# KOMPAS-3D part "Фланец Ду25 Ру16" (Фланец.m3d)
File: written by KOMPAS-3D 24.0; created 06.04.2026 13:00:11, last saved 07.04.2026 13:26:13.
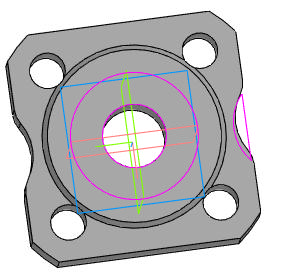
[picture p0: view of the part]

Document properties: Автор: R2D2; Полное имя файла: E:\Работа\Зайцев\Солянка\VSR1-13V-PED-F Клапан запорно-регулирующий DN.ru\DN25\исходные материалы\Фланец.m3d

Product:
- Component [standard]: (unnamed)  | qty 1  | Материал: ВЧ40 ГОСТ 7293-85 (density 7200 kg/m3); Масса: 1.17; additional columns: 25-16-01-1-B-ВЧ40-II-dв 33; Фланец квадратный; ГОСТ 33259-2015
- Part/product: Фланец Ду25 Ру16
    Масса: 0.888787

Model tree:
1. Эскиз:1
2. Элемент выдавливания:1
3. Скругление:1  (with: Ребро.Элемент выдавливания:1)
     Радиус = 10
4. Зеркальный массив:1
5. Экземпляр ( 1 )
6. Экземпляр ( 2 )  (with: Элемент выдавливания:1, Скругление:1)
7. Эскиз:2
8. Элемент выдавливания:2
     Расстояние 1 = -18

Expressions: v108*2
Referenced files in C:\Program Files\ASCON\KOMPAS-3D v24\Libs\PolynomLib\DATA\vault\Methods\Kompas\3D\: PLib_Flange_GOST_33259_1401.m3d
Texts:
  BOSimple***Material:38d6725a-5efe-48e1-b177-a7817acb862a
  BOSimple***PART:3d5c1697-8c1a-4a41-919e-241c28f704d4***SHORTLOC:B6A6_23E38AE8DB154823[II;1;Квадратный;25;16;33;0;ВЧ40 ГОСТ 7293-85]
  Ch34
  Плоскость XY.Начало координат
  Ось Z.Начало координат
  Плоскость ZY.Начало координат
